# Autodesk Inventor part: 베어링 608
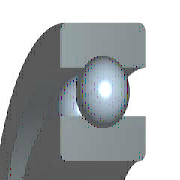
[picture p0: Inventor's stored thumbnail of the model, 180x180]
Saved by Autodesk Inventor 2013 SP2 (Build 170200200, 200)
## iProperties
IsCustomPart: 1
Created: 2012-02
Part Number: 베어링 608
Material: 강철, 연강
Description: 깊은 그루브 볼 베어링
Document SubType Name: Modeling
Standard: KS B 2023
Designer: mduedu
Standards Organization: KS
Language: ko-KR
Size Designation: 608 - 8 x 22 x 7
Categories: <MemberInstance><Categories><Category DisplayName="샤프트 부품" InternalName="7f7aeb1f-a693-4053-b835-cee3144e0d98" Mnemonic="SHFT"><Category DisplayName="베어링" Inter
Density: 1 g/cm^3
Author: mduedu
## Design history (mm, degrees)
sketch "스케치" dims "d0" = 3.64 (= -0.26 x WD + 0.26 x BD)
  geometry: L1 (1.68, 7.5)-(5.32, 7.5); L2 (3.5, 7.5)-(3.5, 5.68); L3 (3.5, 7.5)-(3.5, 9.32); L4 (2.148, 6.282)-(0, 6.282); L5 (0, 4)-(7, 4); L6 (2.148, 8.718)-(0, 8.718); L7 (0, 11)-(7, 11); L8 (7, 4)-(7, 6.282); L9 (4.852, 6.282)-(7, 6.282); L10 (4.852, 8.718)-(7, 8.718); L11 (7, 11)-(7, 8.718); L12 (-1.4, 0)-(8.4, 0) reference; L13 (0, -0.3)-(0, 5.3) reference
  constraints: 22 end point, 4 point on line, 2 collinear, 2 perpendicular, 2 symmetric about line, 1 midpoint, 1 parallel, 14 other
  dimensions: "d9" = 8 diameter of L5 L12 (= WD); "d11" = 22 diameter of L7 L12 (= BD); "d12" = 7 distance between parallel lines of L8 L13 (= KB); "d13" = 12.564 diameter of L9 L12 (= 0.326 x BD + 0.674 x WD)
revolve "본체" stored, may be unused: angle "d6" = 90 deg
revolve "볼" stored, may be unused: angle "d7" = 90 deg
pattern_circular "IDS_ARRAYBALL[SIMPL:T]" dims angle "d3" = 360 deg
body "Solid1"
fillet "모깎기1" dims "d1" = 0.3 (= KRS)
other parameters: "WD" = 8 [user parameter; used in 5 equation terms], "BD" = 22 [user parameter; used in 5 equation terms], "KB" = 7 [user parameter; used in 1 equation term], "KRS" = 0.3 [user parameter; used in 1 equation term], "d4" = 0, "d5" = 0, "d8" = 0, "d14" = 0, "d15" = 0, "BBA" = 0 [user parameter], "BC0" = 1370000 [user parameter], "BC" = 3250000 [user parameter], "BR" = 11 (= 0.5 x BD) [user parameter], "WR" = 4 (= 0.5 x WD) [user parameter]
